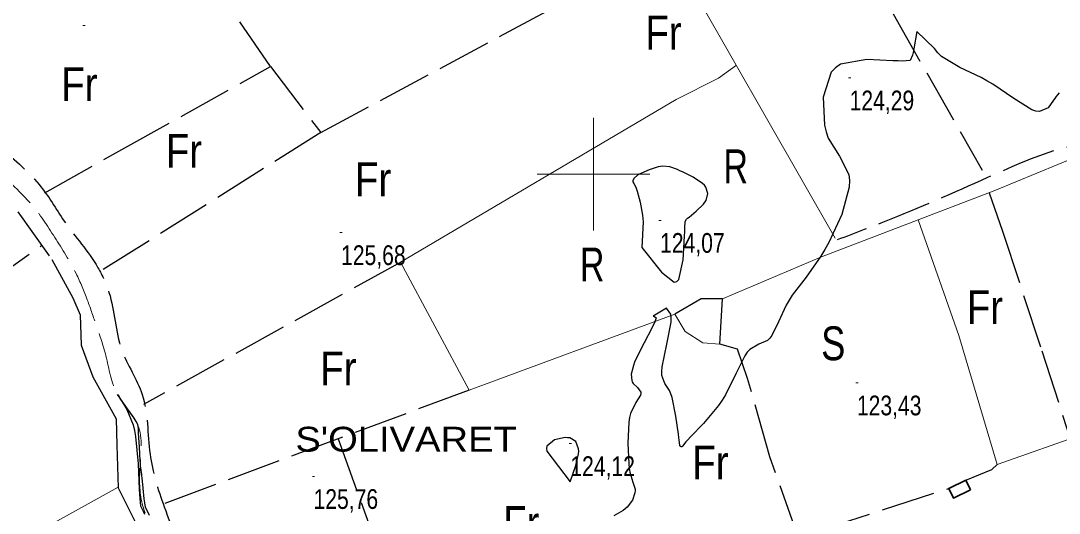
# Model space of a CAD drawing. Extents: x 483855 to 488461, y 4388206 to 4391419.
# Drawn here: x 486246.1 to 486706.5, y 4390349.6 to 4390568 of the extents above; entities that cross this region are included whole.
import ezdxf
from ezdxf.enums import TextEntityAlignment as Align

# ---------------------------------------------------------------- set-up
doc = ezdxf.new("R2010")
doc.units = 0
doc.header["$LTSCALE"] = 4
doc.linetypes.add('LONG_DASHED', pattern=[7.5, 6, -1.5])
for name, color, linetype, lineweight in [('1', 7, 'Continuous', 13), ('15', 7, 'LONG_DASHED', 13), ('25', 7, 'LONG_DASHED', 25), ('38', 7, 'Continuous', 25), ('47', 7, 'Continuous', 35), ('51', 7, 'Continuous', 13), ('7', 7, 'Continuous', 13), ('8', 7, 'Continuous', 25)]:
    doc.layers.add(name, color=color, linetype=linetype, lineweight=lineweight)
doc.layers.add('31', color=7, linetype='Continuous')
doc.layers.add('5', color=7, linetype='Continuous')

msp = doc.modelspace()

# ---------------------------------------------------------------- linework, layer by layer
at = {"layer": '1'}
for p, q in [((486500, 4390525), (486500, 4390475)), ((486475, 4390500), (486525, 4390500))]:
    msp.add_line(p, q, dxfattribs=at)
at = {"layer": '15'}
msp.add_spline([(485988.87, 4391068.04), (485998.94, 4391057.53), (486002.33, 4391047.56), (486012.93, 4391033.93), (486019.04, 4391018.41), (486024.68, 4391004.24), (486026.36, 4390989.16), (486034.27, 4390970.72), (486040.06, 4390957.76), (486055.39, 4390945.7), (486063.13, 4390937.91), (486072.53, 4390923.6), (486082.62, 4390897.51), (486087.3, 4390877.34), (486091.75, 4390862.42), (486096.21, 4390844.8), (486096.99, 4390827.85), (486098.36, 4390814.05), (486099.06, 4390797.32), (486099.09, 4390782.99), (486099.7, 4390771.74), (486102.73, 4390756.37), (486111.25, 4390727.28), (486119.61, 4390707.19), (486127.67, 4390687.77), (486136.4, 4390670.46), (486146.49, 4390645.57), (486156.89, 4390619.63), (486172.84, 4390590.93), (486180.89, 4390576.54), (486187.22, 4390560.95), (486197.89, 4390546.04), (486213.23, 4390527.23), (486226.52, 4390514.2), (486236.37, 4390501.62), (486250.72, 4390486.71), (486261.18, 4390471.95), (486270.65, 4390455.91), (486275.7, 4390444), (486279.62, 4390432.82), (486283.84, 4390419.48), (486289.04, 4390402.23), (486297.99, 4390388.75), (486298.93, 4390369.09), (486300.23, 4390352.82), (486312.94, 4390328.76), (486321.38, 4390309.79), (486332.06, 4390289.33), (486336.71, 4390248.61), (486341.19, 4390211.18), (486345.81, 4390187.19), (486347.48, 4390172.64), (486347.21, 4390157.78), (486346.26, 4390140.53), (486338.86, 4390126.19), (486336.32, 4390120.03), (486336.26, 4390105.41), (486340.56, 4390096.04), (486348.38, 4390083.82), (486353.34, 4390075.2), (486354.36, 4390073.3)], degree=3, dxfattribs=at)
at = {"layer": '25'}
for p, q in [((486356.77, 4390547.65), (486293.99, 4390639.26)), ((486379.1, 4390518.43), (486490.69, 4390578.32)), ((486230.23, 4390450.52), (486255.4, 4390468.44)), ((486414.92, 4390461.12), (486300.51, 4390397.89)), ((486444.91, 4390404.24), (486309.35, 4390353.77))]:
    msp.add_line(p, q, dxfattribs=at)
for points in [[(486588.69, 4390651.04), (486618.05, 4390597.05), (486672.28, 4390501.69)], [(486256.77, 4390491.75), (486290.97, 4390510.93), (486356.77, 4390547.65), (486379.1, 4390518.43), (486281.15, 4390456.67)], [(486675.36, 4390491.75), (486681.25, 4390474.67), (486698.78, 4390421.69), (486711.35, 4390382.65)], [(486244.88, 4390483.25), (486259.92, 4390462.05), (486269.25, 4390445.11), (486272.48, 4390437.54), (486272.88, 4390424.19), (486278.08, 4390410.17), (486288.39, 4390391.43), (486288.71, 4390379.8), (486289.26, 4390360.9), (486299.35, 4390340.74), (486317.49, 4390302.21), (486322.31, 4390290.07), (486328.89, 4390258.65), (486336.61, 4390212.08), (486340.95, 4390173.3), (486340.46, 4390153.95), (486333.9, 4390131.96), (486326.57, 4390115.14), (486328.31, 4390105.92), (486336, 4390083.2), (486334.66, 4390078.1), (486317.33, 4390076.49), (486296.56, 4390071.88), (486282.42, 4390065.98)], [(486590.72, 4390339.21), (486578.25, 4390374.65), (486568.35, 4390409.35), (486563.81, 4390422.3), (486556.06, 4390424.65), (486557.12, 4390444.75), (486547.67, 4390444.7), (486536.01, 4390437.9)], [(486386.83, 4390382.62), (486421.41, 4390286.4), (486411.51, 4390282.11)], [(486665.11, 4390364.29), (486676.61, 4390369), (486678.92, 4390371.19)], [(486529.45, 4390320.71), (486572.15, 4390333.69), (486599.52, 4390341.83), (486657.49, 4390360.65)]]:
    msp.add_lwpolyline(points, dxfattribs=at)
at = {"layer": '38', "linetype": 'LONG_DASHED'}
for points in [[(486219.41, 4390825.8), (486240.87, 4390778.35), (486256.15, 4390746.27), (486296.81, 4390696.53), (486319.66, 4390668.21), (486324.1, 4390662.74), (486324.03, 4390660.56), (486322.61, 4390657.26), (486319.31, 4390655.38), (486264.98, 4390620.79), (486216.8, 4390589.88), (486197.99, 4390579.12), (486194.25, 4390574.01), (486193.4, 4390565.76)], [(486193.4, 4390565.76), (486212.3, 4390545.54), (486236.35, 4390513.02), (486254.31, 4390495.34), (486265.36, 4390479.16), (486280.33, 4390458.48), (486285.22, 4390447.54), (486290.89, 4390422.12), (486299.92, 4390402.33), (486303.42, 4390375.85), (486309.68, 4390352.53), (486321.88, 4390323.15), (486327.83, 4390311.08)], [(486733.35, 4390515.56), (486710.14, 4390511.96), (486677.48, 4390499.68), (486631.87, 4390480.01), (486608.07, 4390470.81)]]:
    msp.add_spline(points, degree=3, dxfattribs=at)
at = {"layer": '47'}
msp.add_lwpolyline([(486667.15, 4390360.02), (486659.53, 4390356.38), (486657.49, 4390360.65), (486665.11, 4390364.29)], close=True, dxfattribs=at)
at = {"layer": '51'}
msp.add_line((486532.74, 4390601.8), (486607.19, 4390471.58), dxfattribs=at)
for points in [[(486536.68, 4390533.09), (486555.48, 4390542.49), (486563.35, 4390548.26)], [(486536.68, 4390533.09), (486414.52, 4390460.88), (486444.92, 4390404.21), (486536.01, 4390437.9), (486540.67, 4390430.25), (486548.48, 4390425.16), (486556.06, 4390424.65)], [(486557.12, 4390444.75), (486601.12, 4390463.26), (486677.98, 4390492.76), (486715.14, 4390508.15), (486719.17, 4390507.29)], [(486643.91, 4390479.68), (486661.89, 4390428.43), (486678.92, 4390371.19), (486718.45, 4390385.16), (486781.12, 4390405.81), (486810.71, 4390417)], [(486156.56, 4390405.55), (486205.92, 4390313.81), (486259.73, 4390344.73), (486289.25, 4390361.18)]]:
    msp.add_lwpolyline(points, dxfattribs=at)
at = {"layer": '7'}
for p, q in [((486273.65, 4390565.89), (486274.65, 4390565.89)), ((486613.05, 4390542.62), (486614.05, 4390542.62)), ((486529.02, 4390479.46), (486530.02, 4390479.46)), ((486387.6, 4390474.03), (486388.6, 4390474.03)), ((486616.27, 4390407.41), (486617.27, 4390407.41)), ((486489.24, 4390380.51), (486490.24, 4390380.51)), ((486375.4, 4390365.92), (486376.4, 4390365.92))]:
    msp.add_line(p, q, dxfattribs=at)
at = {"layer": '8'}
for points in [[(486706.47, 4390535.94), (486705.01, 4390534.2), (486704.5, 4390533.54), (486703.95, 4390532.79), (486701.6, 4390529.42), (486697.66, 4390527.67), (486696.1, 4390527.94), (486694.35, 4390528.54), (486686.35, 4390533.43), (486677, 4390539.83), (486674.4, 4390541.38), (486671.79, 4390542.83), (486662.34, 4390547.25), (486654.3, 4390552.07), (486652.59, 4390553.77), (486651.11, 4390555.63), (486643.28, 4390563.16), (486642.01, 4390555.45), (486641.69, 4390553.93), (486641.39, 4390552.68), (486640.4, 4390550.39), (486636.9, 4390550.11), (486635.02, 4390550.13), (486632.73, 4390550.2), (486621.13, 4390550.77), (486609.54, 4390548.73), (486607.25, 4390547.15), (486605.37, 4390545.12), (486601.89, 4390534.13), (486602.46, 4390521.66), (486603.13, 4390518.71), (486604.01, 4390515.97), (486609.04, 4390507.88), (486613.14, 4390499.85), (486613.45, 4390497.16), (486613.39, 4390494.26), (486610.16, 4390482.1), (486604.31, 4390469.63), (486602.6, 4390466.54), (486600.85, 4390463.61), (486594.21, 4390454.33), (486588.14, 4390446.26), (486586.75, 4390444.09), (486585.49, 4390441.94)], [(486585.49, 4390441.94), (486581.98, 4390434.42), (486579.02, 4390428.43), (486578.11, 4390427.25), (486577.15, 4390426.28), (486573.34, 4390424.52), (486569.29, 4390422.27), (486568.17, 4390421), (486567.07, 4390419.44), (486563.09, 4390411.47), (486558.5, 4390402.13), (486557.01, 4390399.71), (486555.41, 4390397.36), (486548.81, 4390389.49), (486542.97, 4390383.44), (486541.85, 4390382.24), (486540.94, 4390381.26), (486539.45, 4390379.42), (486539.31, 4390379.08), (486539.25, 4390379.03), (486539.19, 4390379.01), (486538.89, 4390379.08), (486538.6, 4390379.26), (486538.54, 4390379.3), (486538.48, 4390379.33), (486538.37, 4390379.42), (486538.32, 4390379.53), (486538.31, 4390379.57), (486538.31, 4390379.62), (486538.3, 4390379.84), (486538.02, 4390381.97), (486537.85, 4390383.22), (486537.62, 4390384.76), (486536.46, 4390392.7), (486534.83, 4390400.89), (486534.31, 4390402.58), (486533.77, 4390404.03), (486531.59, 4390407.18), (486530.29, 4390410.77), (486530.31, 4390412.5), (486530.49, 4390414.54), (486532.51, 4390424.55), (486534.37, 4390434.36), (486534.46, 4390436.27), (486534.36, 4390437.83), (486532.43, 4390440.55), (486526.51, 4390437.04), (486527.02, 4390436.87), (486527.84, 4390436.21), (486527.01, 4390434.09), (486526.48, 4390433.01), (486525.83, 4390431.7), (486522.4, 4390425.18), (486518.93, 4390418.21), (486518.25, 4390416.63), (486517.68, 4390415.19), (486516.65, 4390411.22), (486516.94, 4390408.49), (486517.21, 4390407.83), (486517.56, 4390407.22), (486519.52, 4390405.33), (486520.94, 4390403.34), (486520.95, 4390402.66), (486520.79, 4390401.93), (486518.84, 4390398.79), (486516.43, 4390393.88), (486515.98, 4390392.03), (486515.64, 4390389.97), (486515.18, 4390380.72), (486515.64, 4390371.59), (486515.86, 4390369.59), (486516.13, 4390367.83), (486517.48, 4390363.38), (486518.44, 4390360.37), (486518.46, 4390359.52), (486518.39, 4390358.65), (486517.27, 4390355.45), (486514.91, 4390352.39), (486514.05, 4390351.61), (486513.11, 4390350.87), (486508.98, 4390348.45)], [(486303.21, 4390348.61), (486301.48, 4390352.31), (486301.11, 4390354.24), (486301, 4390355.08), (486300.88, 4390356.06), (486300.39, 4390360.72), (486299.93, 4390365.3), (486299.82, 4390366.23), (486299.73, 4390367.02), (486299.48, 4390368.66), (486299.26, 4390370.67), (486299.18, 4390371.69), (486299.1, 4390372.92), (486298.73, 4390379.05), (486298.38, 4390385.12), (486298.31, 4390386.3), (486298.24, 4390387.28), (486298.08, 4390389.03), (486297.31, 4390390.31), (486296.87, 4390390.98), (486296.32, 4390391.8), (486293.5, 4390395.89), (486290.69, 4390399.91), (486290.16, 4390400.68), (486289.72, 4390401.29), (486289.02, 4390402.26), (486289.01, 4390402.24), (486289.01, 4390402.24), (486289.01, 4390402.23), (486289.02, 4390402.2), (486289.67, 4390401.18), (486290.07, 4390400.54), (486290.57, 4390399.76), (486293.19, 4390395.64), (486295.93, 4390388.84), (486296.5, 4390386.35), (486297, 4390383.6), (486298.11, 4390371.5), (486298.64, 4390360.26), (486298.76, 4390358.05), (486298.87, 4390356.23), (486299.19, 4390352.93), (486300.33, 4390350.49), (486300.97, 4390349.21)]]:
    msp.add_lwpolyline(points, dxfattribs=at)
for points in [[(486521.42, 4390467.51), (486530.16, 4390456.5), (486535.81, 4390452.1), (486536.95, 4390452.37), (486537.91, 4390453.29), (486539.83, 4390462.01), (486540.38, 4390472.48), (486540.48, 4390474.52), (486540.55, 4390476.17), (486540.59, 4390479.02), (486541.28, 4390479.96), (486541.75, 4390480.41), (486542.35, 4390480.94), (486545.54, 4390483.54), (486548.77, 4390486.64), (486549.39, 4390487.48), (486549.89, 4390488.32), (486550.74, 4390491.31), (486549.79, 4390494.22), (486549.16, 4390495.02), (486548.38, 4390495.81), (486544.23, 4390498.61), (486539.49, 4390500.98), (486538.34, 4390501.5), (486537.26, 4390501.96), (486533.91, 4390503.14), (486530.73, 4390503.43), (486529.74, 4390503.34), (486528.72, 4390503.17), (486524.64, 4390501.94), (486520.97, 4390500.32), (486520.19, 4390499.91), (486519.53, 4390499.51), (486518, 4390498.21), (486517.48, 4390497.12), (486517.44, 4390496.85), (486517.46, 4390496.61), (486517.89, 4390495.86), (486518.76, 4390494.19), (486519.05, 4390493.36), (486519.37, 4390492.37), (486520.67, 4390487.48), (486521.74, 4390481.77), (486521.91, 4390480.26), (486522.02, 4390478.78)], [(486489.61, 4390363.53), (486492.19, 4390370.87), (486493.42, 4390375.98), (486493.48, 4390377.17), (486493.42, 4390378.26), (486492.18, 4390381.37), (486489.48, 4390382.99), (486488.5, 4390383.13), (486487.42, 4390383.15), (486482.67, 4390382.11), (486479.38, 4390379.35), (486479.21, 4390378.28), (486479.38, 4390377.08)]]:
    msp.add_lwpolyline(points, close=True, dxfattribs=at)

# ---------------------------------------------------------------- texts
at = {"layer": '31'}
for s, width, p in [('Fr', 0.85, (486531.04, 4390555.2)), ('Fr', 0.85, (486272.1, 4390532.32)), ('Fr', 0.85, (486318.47, 4390502.77)), ('R', 0.75, (486563.07, 4390495.94)), ('Fr', 0.85, (486402.31, 4390490.19)), ('R', 0.75, (486499.43, 4390452.44)), ('Fr', 0.85, (486673.53, 4390433.47)), ('S', 0.8, (486606.29, 4390417.46)), ('Fr', 0.85, (486386.94, 4390406.31)), ('Fr', 0.85, (486551.85, 4390364.6)), ('Fr', 0.85, (486467.99, 4390337.8))]:
    msp.add_text(s, height=15, dxfattribs=dict(at, width=width)).set_placement(p, align=Align.CENTER)
at = {"layer": '5', "width": 1.15}
msp.add_text("S'OLIVARET", height=11, dxfattribs=at).set_placement((486367.85, 4390376.96))
at = {"layer": '7', "width": 0.8}
for s, p in [('124,29', (486613.55, 4390528.25)), ('124,07', (486529.52, 4390465.09)), ('125,68', (486388.1, 4390459.66)), ('123,43', (486616.77, 4390393.04)), ('124,12', (486489.74, 4390366.14)), ('125,76', (486375.9, 4390351.55))]:
    msp.add_text(s, height=8.75, dxfattribs=at).set_placement(p)

doc.saveas('drawing.dxf')
